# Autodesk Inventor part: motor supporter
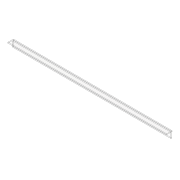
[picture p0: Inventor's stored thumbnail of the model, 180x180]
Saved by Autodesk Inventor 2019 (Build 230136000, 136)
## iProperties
Created: 2019-10
Part Number: motor supporter
Material: PET Plastic
Document SubType Name: Modeling
Designer: hp
Density: 1.541 g/cm^3
Appearance: Polycarbonate - Clear
Author: hp
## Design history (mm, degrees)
sketch "Sketch1"
  geometry: L1 (-24.442, 3.562)-(325.558, 3.562); L2 (325.558, 3.562)-(325.558, -8.438); L3 (325.558, -8.438)-(-24.442, -8.438); L4 (-24.442, -8.438)-(-24.442, 3.562); 1 further point
  constraints: 8 end point, 2 parallel, 1 horizontal, 1 perpendicular
  dimensions: "d0" = 350 distance of L2.end L3.end; "d1" = 12 distance of L1.end L2.end
extrude "Extrusion1" new body sketch "Sketch1" distance "d2" = 2; taper "d3" = 0 deg
sketch "Sketch2"
  geometry: L1 (0, 0.608)-(350, 0.608); L2 (350, 0.608)-(350, -11.392); L3 (350, -11.392)-(0, -11.392); L4 (0, -11.392)-(0, 0.608); 1 further point
  constraints: 8 end point, 2 parallel, 1 horizontal, 1 perpendicular
  dimensions: "d4" = 350 distance of L2.end L3.end; "d5" = 12 distance of L1.end L2.end
extrude "Extrusion2" join sketch "Sketch2" distance "d6" = 2; taper "d7" = 0 deg
body "Solid1"
